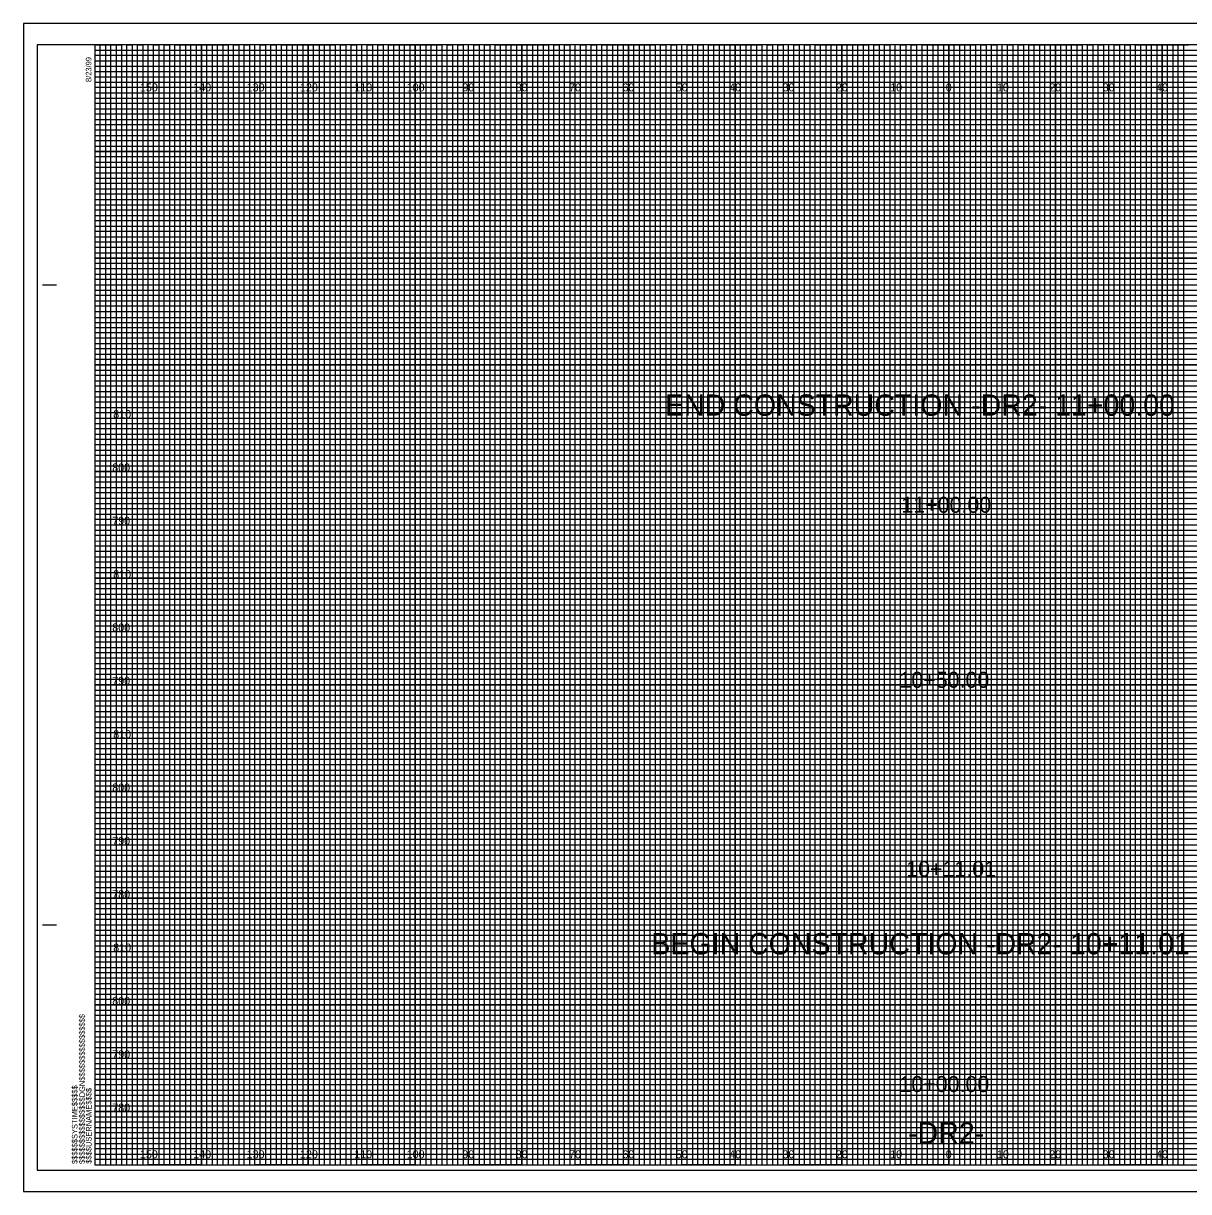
# Model space of a CAD drawing. Extents: x -13 to 323, y -5 to 214.
# Drawn here: x -13.4 to 205, y -5 to 214 of the extents above; entities that cross this region are included whole.
import ezdxf

# ---------------------------------------------------------------- set-up
doc = ezdxf.new("R2010")
doc.units = 0
for name, color, linetype in [('Prop XS Alignment Label', 7, 'Continuous'), ('Prop XS Elevation Labels', 7, 'Continuous'), ('Prop XS Offset Labels', 7, 'Continuous'), ('Prop XS Station Labels', 7, 'Continuous'), ('Sheet Cross Section CELL', 7, 'Continuous'), ('Sheet Cross Section Grid Major CELL', 7, 'Continuous'), ('Sheet Cross Section Grid Middle CELL', 7, 'Continuous'), ('Sheet Cross Section Grid Minor 1 CELL', 7, 'Continuous'), ('Sheet Cross Section Grid Minor 2 CELL', 7, 'Continuous'), ('Sheet Cutting Line CELL', 7, 'Continuous'), ('Sheet DOT Grid CELL', 7, 'Continuous'), ('Sheet Plot Border Inside CELL', 7, 'Continuous'), ('Sheet Plot Border Outside CELL', 7, 'Continuous')]:
    doc.layers.add(name, color=color, linetype=linetype)

msp = doc.modelspace()

# ---------------------------------------------------------------- linework, layer by layer
at = {"layer": 'Sheet Cross Section CELL'}
for p, q in [((-9.8, 165), (-7.3, 165)), ((-9.7, 165), (-7.2, 165)), ((-9.8, 45), (-7.3, 45)), ((-9.7, 45), (-7.2, 45)), ((0, 0), (0, 0)), ((0, 0), (0, 0)), ((0, 0), (0, 0)), ((0, 0), (0, 0)), ((0, 0), (0, 0)), ((0, 0), (0, 0)), ((0, 0), (0, 0))]:
    msp.add_line(p, q, dxfattribs=at)
msp.add_lwpolyline([(320, 210), (0, 210), (0, 0), (320, 0)], close=True, dxfattribs=at)
at = {"layer": 'Sheet Cross Section Grid Major CELL'}
for p, q in [((10, 210), (0, 210)), ((10, 0), (10, 210)), ((30, 210), (20, 210)), ((20, 210), (20, 0)), ((30, 0), (30, 210)), ((50, 210), (40, 210)), ((40, 210), (40, 0)), ((50, 0), (50, 210)), ((70, 210), (60, 210)), ((60, 210), (60, 0)), ((70, 0), (70, 210)), ((90, 210), (80, 210)), ((80, 210), (80, 0)), ((90, 0), (90, 210)), ((110, 210), (100, 210)), ((100, 210), (100, 0)), ((110, 0), (110, 210)), ((130, 210), (120, 210)), ((120, 210), (120, 0)), ((130, 0), (130, 210)), ((150, 210), (140, 210)), ((140, 210), (140, 0)), ((150, 0), (150, 210)), ((170, 210), (160, 210)), ((160, 210), (160, 0)), ((170, 0), (170, 210)), ((190, 210), (180, 210)), ((180, 210), (180, 0)), ((190, 0), (190, 210)), ((210, 210), (200, 210)), ((200, 210), (200, 0)), ((20, 0), (10, 0)), ((40, 0), (30, 0)), ((60, 0), (50, 0)), ((80, 0), (70, 0)), ((100, 0), (90, 0)), ((120, 0), (110, 0)), ((140, 0), (130, 0)), ((160, 0), (150, 0)), ((180, 0), (170, 0)), ((200, 0), (190, 0))]:
    msp.add_line(p, q, dxfattribs=at)
for points in [[(0, 200), (320, 200), (320, 190), (0, 190)], [(0, 180), (320, 180), (320, 170), (0, 170)], [(0, 160), (320, 160), (320, 150), (0, 150)], [(0, 140), (320, 140), (320, 130), (0, 130)], [(0, 120), (320, 120), (320, 110), (0, 110)], [(0, 100), (320, 100), (320, 90), (0, 90)], [(0, 80), (320, 80), (320, 70), (0, 70)], [(0, 60), (320, 60), (320, 50), (0, 50)], [(0, 40), (320, 40), (320, 30), (0, 30)], [(0, 20), (320, 20), (320, 10), (0, 10)]]:
    msp.add_lwpolyline(points, dxfattribs=at)
at = {"layer": 'Sheet Cross Section Grid Middle CELL'}
for points in [[(0, 210), (5, 210), (5, 0), (15, 0), (15, 210), (25, 210), (25, 0), (35, 0), (35, 210), (45, 210), (45, 0), (55, 0), (55, 210), (65, 210), (65, 0), (75, 0), (75, 210), (85, 210), (85, 0), (95, 0), (95, 210), (105, 210), (105, 0), (115, 0), (115, 210), (125, 210), (125, 0), (135, 0), (135, 210), (145, 210), (145, 0), (155, 0), (155, 210), (165, 210), (165, 0), (175, 0), (175, 210), (185, 210), (185, 0), (195, 0), (195, 210), (205, 210)], [(0, 205), (275, 205)], [(0, 185), (320, 185), (320, 195), (0, 195)], [(0, 165), (320, 165), (320, 175), (0, 175)], [(0, 145), (320, 145), (320, 155), (0, 155)], [(0, 125), (320, 125), (320, 135), (0, 135)], [(0, 105), (320, 105), (320, 115), (0, 115)], [(0, 85), (320, 85), (320, 95), (0, 95)], [(0, 65), (320, 65), (320, 75), (0, 75)], [(0, 45), (320, 45), (320, 55), (0, 55)], [(0, 25), (320, 25), (320, 35), (0, 35)], [(0, 5), (320, 5), (320, 15), (0, 15)]]:
    msp.add_lwpolyline(points, dxfattribs=at)
at = {"layer": 'Sheet Cross Section Grid Minor 1 CELL'}
for p, q in [((0, 209), (260, 209)), ((260, 207.98), (0, 207.98)), ((0, 207.98), (0, 207)), ((0, 207), (260, 207)), ((260, 205.89), (0, 205.89)), ((0, 205.89), (0, 204)), ((0, 204), (320, 204))]:
    msp.add_line(p, q, dxfattribs=at)
for points in [[(0, 203), (270, 203), (320, 203), (320, 202), (0, 202)], [(0, 201), (320, 201), (320, 199), (0, 199)], [(0, 198), (320, 198), (320, 197), (0, 196.98)], [(0, 196), (320, 196), (320, 194), (0, 194)], [(0, 193), (320, 193), (320, 192), (0, 192)], [(0, 191), (320, 191), (320, 189), (0, 189)], [(0, 188), (320, 188), (320, 187), (0, 187)], [(0, 186), (320, 186), (320, 184), (0, 184)], [(0, 183), (320, 183), (320, 182), (0, 182)], [(0, 181), (320, 181), (320, 179), (0, 179)], [(0, 178), (320, 178), (320, 177), (0, 177)], [(0, 176), (320, 176), (320, 173.95), (320, 173), (320, 172), (0, 172)], [(0, 174), (320, 174), (320, 173), (0, 173)], [(0, 171), (320, 171), (320, 169), (0, 169.03)], [(0, 169.03), (320, 169), (320, 168), (0, 168)], [(0, 167), (320, 167), (320, 166), (0, 166)], [(0, 164), (320, 164), (320, 163), (0, 163)], [(0, 162), (320, 162), (320, 161), (0, 161)], [(-0.07, 158.89), (320, 158.89), (320, 157.88), (-0.07, 157.88)], [(0, 157), (320, 157), (320, 156), (0, 156)], [(0, 154), (320, 154), (320, 153), (0, 153)], [(0, 152), (320, 152), (320, 151), (0, 151)], [(0, 149), (320, 149), (320, 148), (0, 148)], [(0, 147), (320, 147), (320, 146), (0, 146)], [(0, 144), (320, 144), (320, 143), (0, 143)], [(0, 142), (320, 142), (320, 141), (0, 141)], [(0, 139), (320, 139), (319.99, 137.98), (0, 138)], [(0, 137), (320, 137), (320, 136), (0, 136)], [(0, 134), (320, 134), (320, 133), (0, 133)], [(0, 132), (320, 132), (320, 131), (0, 131)], [(0, 129), (320, 129), (320, 128), (0, 128)], [(0, 127), (320, 127), (320, 126), (0, 126)], [(0, 124), (320, 124), (320, 123), (0, 123)], [(0, 122), (320, 122), (320, 121), (0, 121)], [(0, 119), (320, 119), (320, 118), (0, 118)], [(0, 116.99), (320.07, 116.91), (320, 116), (0, 116)], [(0, 114), (320, 114), (320, 113), (0, 113)], [(0, 112), (320, 112), (320, 111), (0, 111)], [(0, 109), (320, 109), (320, 108), (0, 108)], [(0, 107), (320, 107), (320, 106), (0, 106)], [(0, 104), (320, 104), (320, 103), (0, 103)], [(0, 102), (320, 102), (320, 101), (0, 101)], [(0, 99), (320, 99), (320, 98), (0, 98)], [(0, 97), (320, 97), (320, 96), (0, 96)], [(0, 94), (320, 94), (320, 93), (0, 93)], [(0, 92), (320, 92), (320, 91), (0, 91)], [(0, 89), (320, 89), (320, 88), (0, 88)], [(0, 87), (320, 87), (320, 86), (0, 86)], [(0, 84), (320, 84), (320, 83), (0, 83)], [(0, 82), (320, 82), (320, 81), (0, 81)], [(0, 79), (320, 79), (319.99, 77.98), (0, 78)], [(0, 77), (320, 77), (320, 76), (0, 76)], [(0, 74), (320, 74), (320, 73), (0, 73)], [(0, 72), (320, 72), (320, 71), (0, 71)], [(0, 69), (320, 69), (320, 68), (0, 68)], [(0, 67), (320, 67), (320, 66), (0, 66)], [(0, 64), (320, 64), (320, 63), (0, 63)], [(0, 62), (320, 62), (320, 61), (0, 61)], [(0, 59), (320, 59), (320, 58), (0, 58)], [(0, 56.99), (320.07, 56.91), (320, 56), (0, 56)], [(0, 54), (320, 54), (320, 53), (0, 53)], [(0, 52), (320, 52), (320, 51), (0, 51)], [(0, 49), (320, 49), (320, 48), (0, 48)], [(0, 47), (320, 47), (320, 46), (0, 46)], [(0, 44), (320, 44), (320, 43), (0, 43)], [(0, 42), (320, 42), (320, 41), (0, 41)], [(0, 39), (320, 39), (320, 38), (0, 38)], [(0, 37), (320, 37), (320, 36), (0, 36)], [(0, 34), (320, 34), (320, 33), (0, 33)], [(0, 32), (320, 32), (320, 31), (0, 31)], [(0, 29), (320, 29), (320, 28), (0, 28)], [(0, 27), (320, 27), (320, 26), (0, 26)], [(0, 24), (320, 24), (320, 23), (0, 23)], [(0, 22), (320, 22), (320, 21), (0, 21)], [(0, 19), (320, 19), (320, 18), (0, 18)], [(0, 17), (320, 17), (320, 16), (0, 16)], [(0, 14), (320, 14), (320, 13), (0, 13)], [(0, 12), (320, 12), (320, 11), (0, 11)], [(0, 9), (320, 9), (320, 8), (0, 8)], [(0, 7), (320, 7), (320, 6), (0, 6)], [(0, 4), (320, 4), (320, 3), (0, 3)], [(0, 2), (320, 2), (320, 1), (0, 1)]]:
    msp.add_lwpolyline(points, dxfattribs=at)
at = {"layer": 'Sheet Cross Section Grid Minor 2 CELL'}
for points in [[(0, 0), (1, 0), (1, 210), (2, 210), (2, 0)], [(2, 0), (3, 0), (3, 210), (4, 210), (4, 0)], [(5, 0), (6, 0), (6, 210), (7, 210), (7, 0)], [(7, 0), (8, 0), (8, 210), (9, 210), (9, 0)], [(10, 0), (11, 0), (11, 210), (12, 210), (12, 0)], [(12, 0), (13, 0), (13, 210), (14, 210), (14, 0)], [(15, 0), (16, 0), (16, 210), (17, 210), (17, 0)], [(17, 0), (18, 0), (18, 210), (19, 210), (19, 0)], [(20, 0), (21, 0), (21, 210), (22, 210), (22, 0)], [(22, 0), (23, 0), (23, 210), (24, 210), (24, 0)], [(25, 0), (26, 0), (26, 210), (27, 210), (27, 0)], [(27, 0), (28, 0), (28, 210), (29, 210), (29, 0)], [(30, 0), (31, 0), (31, 210), (32, 210), (32, 0)], [(32, 0), (33, 0), (33, 210), (34, 210), (34, 0)], [(35, 0), (36, 0), (36, 210), (37, 210), (37, 0)], [(37, 0), (38, 0), (38, 210), (39, 210), (39, 0)], [(40, 0), (41, 0), (41, 210), (42, 210), (42, 0)], [(42, 0), (43, 0), (43, 210), (44, 210), (44, 0)], [(45, 0), (46, 0), (46, 210), (47, 210), (47, 0)], [(47, 0), (48, 0), (48, 210), (49, 210), (49, 0)], [(50, 0), (51, 0), (51, 210), (52, 210), (52, 0)], [(52, 0), (53, 0), (53, 210), (54, 210), (54, 0)], [(55, 0), (56, 0), (56, 210), (57, 210), (57, 0)], [(57, 0), (58, 0), (58, 210), (59, 210), (59, 0)], [(60, 0), (61, 0), (61, 210), (62, 210), (62, 0)], [(62, 0), (63, 0), (63, 210), (64, 210), (64, 0)], [(65, 0), (66, 0), (66, 210), (67, 210), (67, 0)], [(67, 0), (68, 0), (68, 210), (69, 210), (69, 0)], [(70, 0), (71, 0), (71, 210), (72, 210), (72, 0)], [(72, 0), (73, 0), (73, 210), (74, 210), (74, 0)], [(75, 0), (76, 0), (76, 210), (77, 210), (77, 0)], [(77, 0), (78, 0), (78, 210), (79, 210), (79, 0)], [(80, 0), (81, 0), (81, 210), (82, 210), (82, 0)], [(82, 0), (83, 0), (83, 210), (84, 210), (84, 0)], [(85, 0), (86, 0), (86, 210), (87, 210), (87, 0)], [(87, 0), (88, 0), (88, 210), (89, 210), (89, 0)], [(90, 0), (91, 0), (91, 210), (92, 210), (92, 0)], [(92, 0), (93, 0), (93, 210), (94, 210), (94, 0)], [(95, 0), (96, 0), (96, 210), (97, 210), (97, 0)], [(97, 0), (98, 0), (98, 210), (99, 210), (99, 0)], [(100, 0), (101, 0), (101, 210), (102, 210), (102, 0)], [(102, 0), (103, 0), (103, 210), (104, 210), (104, 0)], [(105, 0), (106, 0), (106, 210), (107, 210), (107, 0)], [(107, 0), (108, 0), (108, 210), (109, 210), (109, 0)], [(110, 0), (111, 0), (111, 210), (112, 210), (112, 0)], [(112, 0), (113, 0), (113, 210), (114, 210), (114, 0)], [(115, 0), (116, 0), (116, 210), (117, 210), (117, 0)], [(117, 0), (118, 0), (118, 210), (119, 210), (119, 0)], [(120, 0), (121, 0), (121, 210), (122, 210), (122, 0)], [(122, 0), (123, 0), (123, 210), (124, 210), (124, 0)], [(125, 0), (126, 0), (126, 210), (127, 210), (127, 0)], [(127, 0), (128, 0), (128, 210), (129, 210), (129, 0)], [(130, 0), (131, 0), (131, 210), (132, 210), (132, 0)], [(132, 0), (133, 0), (133, 210), (134, 210), (134, 0)], [(135, 0), (136, 0), (136, 210), (137, 210), (137, 0)], [(137, 0), (138, 0), (138, 210), (139, 210), (139, 0)], [(140, 0), (141, 0), (141, 210), (142, 210), (142, 0)], [(142, 0), (143, 0), (143, 210), (144, 210), (144, 0)], [(145, 0), (146, 0), (146, 210), (147, 210), (147, 0)], [(147, 0), (148, 0), (148, 210), (149, 210), (149, 0)], [(150, 0), (151, 0), (151, 210), (152, 210), (152, 0)], [(152, 0), (153, 0), (153, 210), (154, 210), (154, 0)], [(155, 0), (156, 0), (156, 210), (157, 210), (157, 0)], [(157, 0), (158, 0), (158, 210), (159, 210), (159, 0)], [(160, 0), (161, 0), (161, 210), (162, 210), (162, 0)], [(162, 0), (163, 0), (163, 210), (164, 210), (164, 0)], [(165, 0), (166, 0), (166, 210), (167, 210), (167, 0)], [(167, 0), (168, 0), (168, 210), (169, 210), (169, 0)], [(170, 0), (171, 0), (171, 210), (172, 210), (172, 0)], [(172, 0), (173, 0), (173, 210), (174, 210), (174, 0)], [(175, 0), (176, 0), (176, 210), (177, 210), (177, 0)], [(177, 0), (178, 0), (178, 210), (179, 210), (179, 0)], [(180, 0), (181, 0), (181, 210), (182, 210), (182, 0)], [(182, 0), (183, 0), (183, 210), (184, 210), (184, 0)], [(185, 0), (186, 0), (186, 210), (187, 210), (187, 0)], [(187, 0), (188, 0), (188, 210), (189, 210), (189, 0)], [(190, 0), (191, 0), (191, 210), (192, 210), (192, 0)], [(192, 0), (193, 0), (193, 210), (194, 210), (194, 0)], [(195, 0), (196, 0), (196, 210), (197, 210), (197, 0)], [(197, 0), (198, 0), (198, 210), (199, 210), (199, 0)], [(200, 0), (201, 0), (201, 210), (202, 210), (202, 0)], [(202, 0), (203, 0), (203, 210), (204, 210), (204, 0)]]:
    msp.add_lwpolyline(points, dxfattribs=at)
at = {"layer": 'Sheet Cutting Line CELL'}
for p, q in [((323.3, 214), (-13.4, 214)), ((-13.4, 214), (-13.4, -5)), ((-13.4, -5), (323.3, -5))]:
    msp.add_line(p, q, dxfattribs=at)
at = {"layer": 'Sheet DOT Grid CELL'}
for p, q in [((10, 0), (10, 210)), ((20, 0), (20, 210)), ((30, 0), (30, 210)), ((40, 0), (40, 210)), ((50, 0), (50, 210)), ((60, 0), (60, 210)), ((70, 0), (70, 210)), ((80, 0), (80, 210)), ((90, 0), (90, 210)), ((100, 0), (100, 210)), ((110, 0), (110, 210)), ((120, 0), (120, 210)), ((130, 0), (130, 210)), ((140, 0), (140, 210)), ((150, 0), (150, 210)), ((160, 0), (160, 210)), ((170, 0), (170, 210)), ((180, 0), (180, 210)), ((190, 0), (190, 210)), ((200, 0), (200, 210)), ((0, 200), (320, 200)), ((0, 190), (320, 190)), ((0, 180), (320, 180)), ((0, 170), (320, 170)), ((0, 160), (320, 160)), ((0, 150), (320, 150)), ((0, 140), (320, 140)), ((0, 130), (320, 130)), ((0, 120), (320, 120)), ((0, 110), (320, 110)), ((0, 100), (320, 100)), ((0, 90), (320, 90)), ((0, 80), (320, 80)), ((0, 70), (320, 70)), ((0, 60), (320, 60)), ((0, 50), (320, 50)), ((0, 40), (320, 40)), ((0, 30), (320, 30)), ((0, 20), (320, 20)), ((0, 10), (320, 10))]:
    msp.add_line(p, q, dxfattribs=at)
at = {"layer": 'Sheet Plot Border Inside CELL'}
msp.add_lwpolyline([(-10.8, -1), (322.4, -1), (322.4, 210), (-10.8, 210)], close=True, dxfattribs=at)
at = {"layer": 'Sheet Plot Border Outside CELL'}
msp.add_lwpolyline([(-13.4, -5), (323.3, -5), (323.3, 214), (-13.4, 214)], close=True, dxfattribs=at)

# ---------------------------------------------------------------- texts
at = {"layer": 'Prop XS Alignment Label'}
for s, p in [('END CONSTRUCTION -DR2- 11+00.00', (106.84, 140.44)), ('BEGIN CONSTRUCTION -DR2- 10+11.01', (104.28, 39.47)), ('-DR2-', (152.4, 4))]:
    msp.add_text(s, height=4, dxfattribs=at).set_placement(p)
at = {"layer": 'Prop XS Elevation Labels'}
for s, p in [('810', (3.44, 140)), ('800', (3.26, 130)), ('790', (3.26, 120)), ('810', (3.44, 110)), ('800', (3.26, 100)), ('790', (3.26, 90)), ('810', (3.44, 80)), ('800', (3.26, 70)), ('790', (3.26, 60)), ('780', (3.26, 50)), ('810', (3.44, 40)), ('800', (3.26, 30)), ('790', (3.26, 20)), ('780', (3.26, 10))]:
    msp.add_text(s, height=1.5, dxfattribs=at).set_placement(p)
at = {"layer": 'Prop XS Offset Labels'}
for s, p in [('150', (8.44, 201.25)), ('140', (18.44, 201.25)), ('130', (28.44, 201.25)), ('120', (38.44, 201.25)), ('110', (48.62, 201.25)), ('100', (58.44, 201.25)), ('90', (68.86, 201.25)), ('80', (78.86, 201.25)), ('70', (88.86, 201.25)), ('60', (98.86, 201.25)), ('50', (108.86, 201.25)), ('40', (118.86, 201.25)), ('30', (128.86, 201.25)), ('20', (138.86, 201.25)), ('10', (149.04, 201.25)), ('0', (159.45, 201.25)), ('0', (159.45, 201.25)), ('10', (169.04, 201.25)), ('20', (178.86, 201.25)), ('30', (188.86, 201.25)), ('40', (198.86, 201.25)), ('150', (8.44, 1.25)), ('140', (18.44, 1.25)), ('130', (28.44, 1.25)), ('120', (38.44, 1.25)), ('110', (48.62, 1.25)), ('100', (58.44, 1.25)), ('90', (68.86, 1.25)), ('80', (78.86, 1.25)), ('70', (88.86, 1.25)), ('60', (98.86, 1.25)), ('50', (108.86, 1.25)), ('40', (118.86, 1.25)), ('30', (128.86, 1.25)), ('20', (138.86, 1.25)), ('10', (149.04, 1.25)), ('0', (159.45, 1.25)), ('0', (159.45, 1.25)), ('10', (169.04, 1.25)), ('20', (178.86, 1.25)), ('30', (188.86, 1.25)), ('40', (198.86, 1.25))]:
    msp.add_text(s, height=1.5, dxfattribs=at).set_placement(p)
at = {"layer": 'Prop XS Station Labels'}
for s, p in [('11+00.00', (151.13, 122.25)), ('10+50.00', (150.77, 89.45)), ('10+11.01', (152.04, 54)), ('10+00.00', (150.77, 13.67))]:
    msp.add_text(s, height=3, dxfattribs=at).set_placement(p)
at = {"layer": 'Sheet Cross Section CELL'}
for s, p in [('8/23/99', (-0.65, 203)), ('$$$$$$$$$$$$$$$$DGN$$$$$$$$$$$$$$$$', (-1.88, 0.18)), ('$$$$$$SYSTIME$$$$$', (-3.26, 0.18)), ('$$$$USERNAME$$$$', (-0.62, 0.23))]:
    msp.add_text(s, height=1.05, rotation=90, dxfattribs=at).set_placement(p)

doc.saveas('drawing.dxf')
